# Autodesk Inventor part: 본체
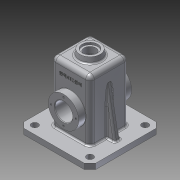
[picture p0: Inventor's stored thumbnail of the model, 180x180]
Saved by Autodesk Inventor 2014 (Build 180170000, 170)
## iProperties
Created: 2016-02
Part Number: 본체
Material: 알루미늄 6061
Document SubType Name: Modeling
Designer: 703-05
Density: 2.71 g/cm^3
Appearance: 알루미늄 - 평지
Mass: 935.961 g
Surface Area: 1045.55 cm^2
Volume: 345.373 cm^3
Author: 703-05
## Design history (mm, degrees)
sketch "스케치1"
  geometry: L1 (-65, 65)-(65, 65); L2 (65, 65)-(65, -65); L3 (65, -65)-(-65, -65); L4 (-65, -65)-(-65, 65); L5 (-65, 65)-(65, -65); L6 (65, 65)-(-65, -65); 1 further point
  constraints: 12 end point, 2 midpoint, 2 parallel, 1 horizontal, 1 perpendicular
  dimensions: "d0" = 130 distance of L2.end L3.end; "d1" = 130 distance of L1.end L2.end
extrude "돌출1" new body sketch "스케치1" distance "d2" = 10; taper "d3" = 0 deg
sketch "스케치2"
  geometry: L1 (-35, 35)-(35, 35); L2 (35, 35)-(35, -35); L3 (35, -35)-(-35, -35); L4 (-35, -35)-(-35, 35); L5 (-35, 35)-(35, -35); L6 (35, 35)-(-35, -35); 1 further point
  constraints: 12 end point, 2 midpoint, 2 parallel, 1 horizontal, 1 perpendicular
  dimensions: "d4" = 70 distance of L2.end L3.end; "d5" = 70 distance of L1.end L2.end
extrude "돌출2" join sketch "스케치2" distance "d6" = 110; taper "d7" = 0 deg
fillet "모깎기1" dims "d8" = 8
fillet "모깎기2" dims "d9" = 8
chamfer "모따기1" distance "d10" = 10; stored, may be unused: second distance "d11" = 2, angle "d12" = 45 deg
sketch "스케치3"
  geometry: L1 (-65, 55)-(-65, -55) reference; L2 (-55, -65)-(55, -65) reference; L3 (65, -55)-(65, 55) reference; L4 (55, 65)-(-55, 65) reference; 5 further points
  constraints: 2 horizontal alignment, 2 vertical alignment
  dimensions: "d13" = 15 distance from line of L4 point (-50, 50); "d14" = 15 distance from line of L1 point (-50, 50); "d15" = 15 distance from line of L2 point (-50, -50); "d16" = 15 distance from line of L3 point (50, -50)
hole "구멍1" sketch "스케치3" at (-50, 50), (50, 50), (50, -50), (-50, -50) diameter "d17" = 12; stored, may be unused: countersink angle "d21" = 90 deg, drill point angle "d23" = 118 deg; dims "d18" = 6, "d19" = 4, "d20" = 2, "d22" = 8
sketch "스케치4"
  geometry: L1 (-55, 10)-(55, 10) reference; L2 (35, 10)-(35, 112) reference; L3 (-35, 112)-(-35, 10) reference; L4 (50, 10)-(35, 95.069); L5 (-65, 10)-(-65, 0) reference; L6 (65, 0)-(65, 10) reference; 1 further point
  constraints: 2 end point, 2 point on line
  dimensions: "d24" = 100 deg angle of L1 L4; "d27" = 15 distance from line of L6 L4.start
feature "리브1" sketch "스케치4" dims "d28" = 1, "d29" = 10, "d30" = 0, "d31" = 0, "d32" = 1, "d33" = 1
fillet "모깎기3" dims "d34" = 3
fillet "모깎기4" dims "d35" = 3
sketch "스케치5"
  geometry: L1 (-55, 0)-(55, 0) reference; L2 (-27, 120)-(27, 120) reference; L3 (-30, 0)-(-30, 115); L4 (-30, 115)-(30, 115); L5 (30, 115)-(30, 0); L6 (-35, 13)-(-35, 112) reference; L7 (35, 112)-(35, 13) reference; 1 further point
  constraints: 6 end point, 3 perpendicular, 2 point on line
  dimensions: "d36" = 5 distance between parallel lines of L6 L3; "d37" = 5 distance between parallel lines of L7 L5; "d38" = 5 distance between parallel lines of L4 L2
extrude "돌출3" cut sketch "스케치5" stored distance "d39" = 60; taper "d40" = 0 deg
fillet "모깎기5" dims "d41" = 3
fillet "모깎기6" dims "d42" = 3
sketch "스케치6"
  geometry: C1 r 20 at (0, 0); 1 further point
  constraints: 1 centre point, 1 coincident
  dimensions: "d43" = 40 diameter of C1
extrude "돌출4" join sketch "스케치6" distance "d44" = 10; taper "d45" = -10 deg
fillet "모깎기7" dims "d46" = 3
hole "구멍2" diameter "d49" = 21; stored, may be unused: countersink angle "d53" = 90 deg, drill point angle "d55" = 118 deg; dims "d47" = 10, "d48" = 10, "d50" = 6, "d51" = 28, "d52" = 4, "d54" = 8
sketch "스케치7"
  geometry: L1 (82, -112)-(-28, -112) reference; C1 r 27.5 at (27, -57); 2 further points
  constraints: 1 centre point, 1 midpoint, 1 vertical alignment
  dimensions: "d56" = 55 diameter of C1; "d57" = 55 distance from line of L1 C1.centre
extrude "돌출5" join sketch "스케치7" distance "d58" = 13; taper "d59" = 0 deg
sketch "스케치8"
  geometry: L1 (-48, 82.5)-(-48, 27.5) reference; L2 (48, 82.5)-(48, 27.5) reference; L3 (48, 55)-(-48, 55); L4 (-23, 55)-(-23, 75.5); L5 (-30, 112)-(-30, 0) reference; L6 (30, 0)-(30, 112) reference; L7 (-23, 75.5)-(-30, 82.5); L8 (23, 55)-(23, 75.5); L9 (23, 75.5)-(30, 82.5); L10 (-30, 82.5)-(-30, 55); L11 (30, 82.5)-(30, 55); 1 further point
  constraints: 14 end point, 8 point on line, 2 equal length, 2 midpoint, 1 parallel, 1 perpendicular
  dimensions: "d60" = 7 distance between parallel lines of L5 L4; "d61" = 7 distance between parallel lines of L6 L8; "d62" = 135 deg angle of L5 L7; "d64" = 55 diameter of L7.end L3
revolve "회전1" sketch "스케치8" stored, may be unused: angle "d65" = 90 deg
hole "구멍3" diameter "d68" = 32; stored, may be unused: countersink angle "d72" = 90 deg, drill point angle "d74" = 118 deg; dims "d66" = 10, "d67" = 10, "d69" = 6, "d70" = 28, "d71" = 4, "d73" = 8
chamfer "모따기2" distance "d75" = 1; stored, may be unused: second distance "d76" = 2, angle "d77" = 45 deg
sketch "스케치9" dims "d78" = 45
  geometry: L1 (0, 0)-(0, 22.5); C1 r 17 at (0, 0) reference; 2 further points
  constraints: 2 coincident, 2 end point, 1 vertical, 1 vertical alignment, 2 other
hole "구멍4" sketch "스케치9" at (0, 22.5) diameter "d79" = 3.242; stored, may be unused: countersink angle "d83" = 90 deg, drill point angle "d85" = 118 deg; dims "d80" = 8, "d81" = 28, "d82" = 4, "d84" = 10
fillet "모깎기8" dims "d86" = 0.5
node "작업 평면1"
sketch "스케치10"
  geometry: L1 (35, 13)-(35, 112) reference; L2 (-18.237, 130)-(18.237, 130) reference; 2 further points
  constraints: 1 other
  dimensions: "d92" = 35 distance from line of L1 point (0, 100); "d93" = 30 distance from line of L2 point (0, 100)
feature "엠보싱1" sketch "스케치10" dims "d0" = 130, "d1" = 130, "d94" = 0.5, "d95" = 0
node "솔리드1"
mirror "대칭1"
mirror "대칭2"
pattern_circular "원형 패턴1" dims angle "d88" = 360 deg
mirror "대칭3"
other parameters: "d90" = -40.25
